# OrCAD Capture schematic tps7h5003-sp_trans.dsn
size Custom; title: TPS7H5003-SP Radiation-Hardness-Assured 2-MHz; rev: *; note: Datasheet: SLVSF07A    EVM User Guide: SLVUCD0; note: Current Mode PWM Controller
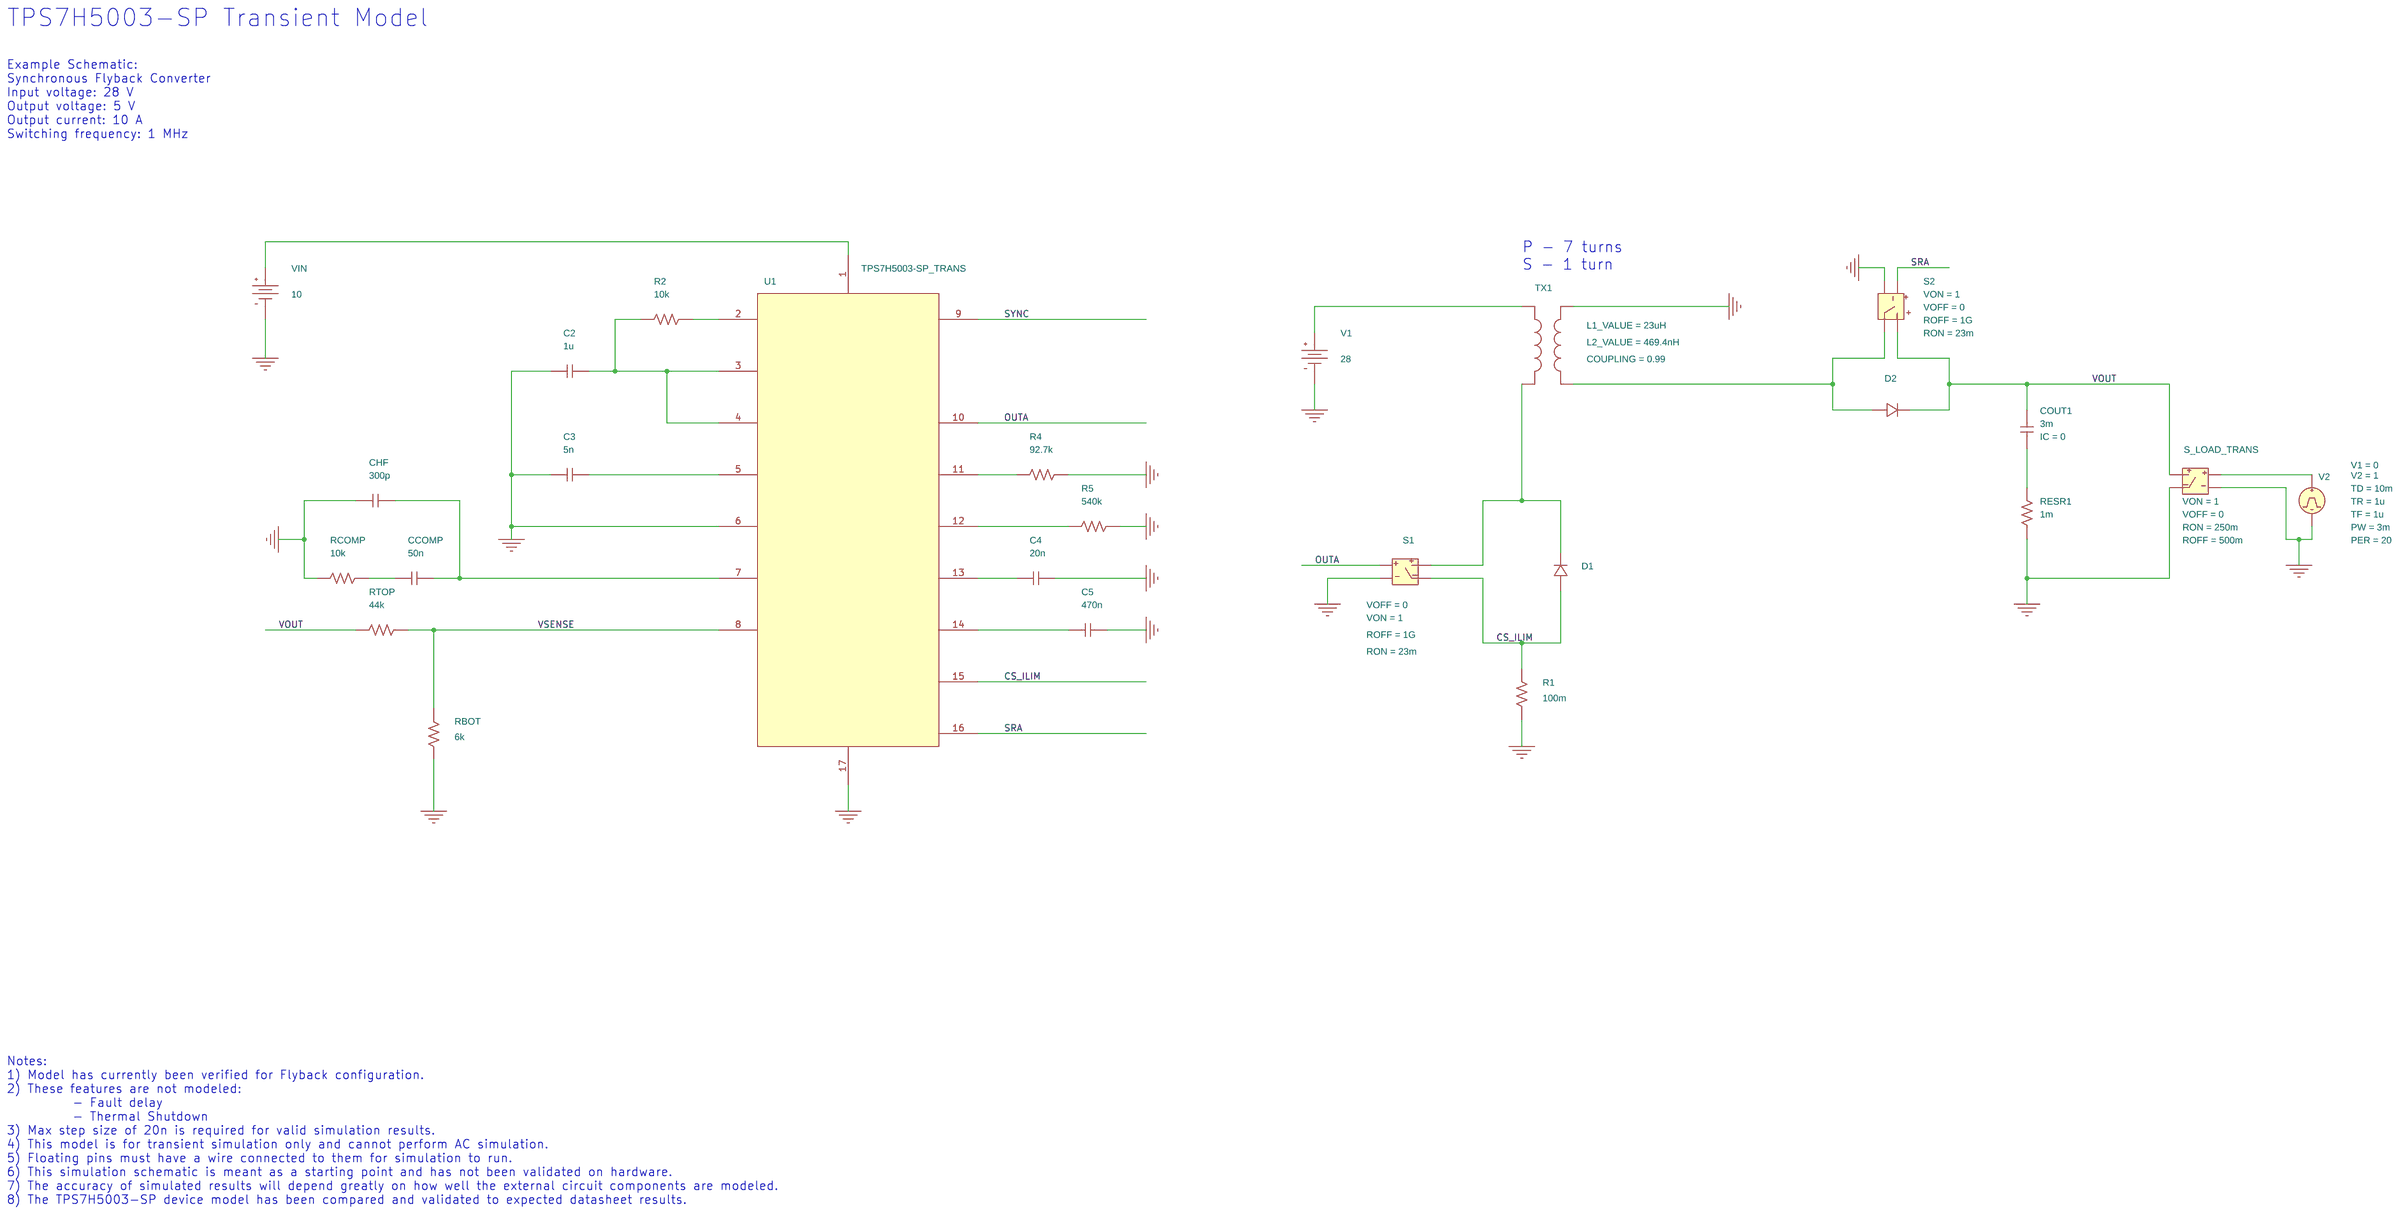
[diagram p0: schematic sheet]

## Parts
C2  1u  [cap196]
C3  5n  [cap196]
C4  20n  [cap196]
C5  470n  [cap196]
CCOMP  50n  [cap196]
CHF  300p  [cap196]
COUT1  3m  [cap196]
D1  Dbreak
D2  Dbreak
R1  100m  [AXRC05]
R2  10k  [AXRC05]
R4  92.7k  [AXRC05]
R5  540k  [AXRC05]
RBOT  6k  [AXRC05]
RCOMP  10k  [AXRC05]
RESR1  1m  [AXRC05]
RTOP  44k  [AXRC05]
S1  S
S2  S
S_LOAD_TRANS  S
TX1  XFRM_LINEAR
U1  TPS7H5003-SP_TRANS
V1  VDC
V2  VPULSE
VIN  VDC

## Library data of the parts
C2-C5 CCOMP CHF = C
COUT1 = C: IC: 0
D1 D2 = Dbreak
R1 R2 R4 R5 RBOT RCOMP RESR1 RTOP = R
S1 S2 = S: ROFF: 1G; RON: 23m; VOFF: 0; VON: 1
S_LOAD_TRANS = S: ROFF: 500m; RON: 250m; VOFF: 0; VON: 1
TX1 = XFRM_LINEAR: COUPLING: 0.99; L1_VALUE: 23uH; L2_VALUE: 469.4nH
U1 = TPS7H5003-SP_TRANS_2
V1 = VDC: DC: 28
V2 = VPULSE: PER: 20; PW: 3m; TD: 10m; TF: 1u; TR: 1u; V1: 0; V2: 1
VIN = VDC: DC: 10

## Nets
0: C2.2 C3.2 C4.1 C5.1 CHF.2 R1.1 R4.1 R5.1 RBOT.2 RCOMP.2 RESR1.1 S1.1(2) S2.1(2) S_LOAD_TRANS.1(2) S_LOAD_TRANS.3(4) TX1.3 U1.6(FAULT) U1.17(AVSS) V1.1(-) V2.2(-) VIN.1(-)
CS_ILIM: D1.0(1) R1.2 S1.3(4) U1.15(CS_ILIM)
OUTA: S1.0(1) U1.10(OUTA)
SRA: S2.0(1) U1.16(SRA)
SYNC: U1.9(SYNC)
VOUT: COUT1.2 D2.1(2) RTOP.2 S2.2(3) S_LOAD_TRANS.2(3)
VSENSE: RBOT.1 RTOP.1 U1.8(VSENSE)
N16778093: TX1.1 V1.0(+)
N16778118: D1.1(2) S1.2(3) TX1.2
N16778171: U1.1(VIN) VIN.0(+)
N16778249: C2.1 R2.2 U1.3(VLDO) U1.4(DCL)
N16778253: R2.1 U1.2(EN)
N16778390: C3.1 U1.5(HICC)
N16778393: R4.2 U1.11(RT)
N16778413: CCOMP.1 CHF.1 U1.7(COMP)
N16778447: R5.2 U1.12(RSC)
N16778537: CCOMP.2 RCOMP.1
N16778545: C4.2 U1.13(SS)
N16778591: COUT1.1 RESR1.2
N16778612: C5.2 U1.14(REFCAP)
N16778649: S_LOAD_TRANS.0(1) V2.1(+)
N16778756: D2.0(1) S2.3(4) TX1.4

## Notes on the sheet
- TPS7H5003-SP Transient Model
- Example Schematic:
  Synchronous Flyback Converter
  Input voltage: 28 V
  Output voltage: 5 V
  Output current: 10 A
  Switching frequency: 1 MHz
- P - 7 turns
  S - 1 turn
- Notes:
  1) Model has currently been verified for Flyback configuration.
  2) These features are not modeled:
            - Fault delay
            - Thermal Shutdown
  3) Max step size of 20n is required for valid simulation results.
  4) This model is for transient simulation only and cannot perform AC simulation.
  5) Floating pins must have a wire connected to them for simulation to run.
  6) This simulation schematic is meant as a starting point and has not been validated on hardware.
  7) The accuracy of simulated results will depend greatly on how well the external circuit components are modeled.
  8) The TPS7H5003-SP device model has been compared and validated to expected datasheet results.
